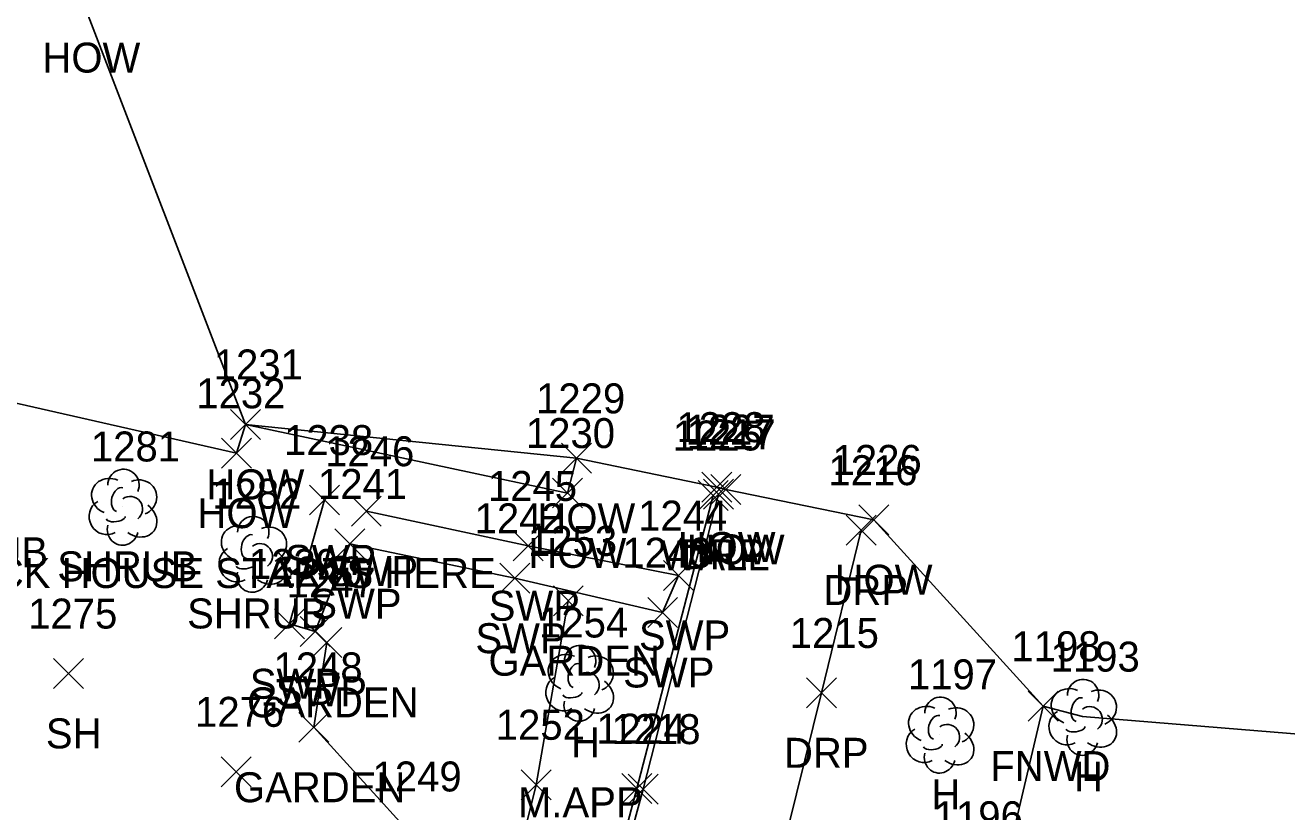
# Model space of a CAD drawing. Extents: x 1616726 to 1619875, y 273782 to 276557.
# Drawn here: x 1617199.2 to 1617283.4, y 276182.4 to 276234.9 of the extents above; entities that cross this region are included whole.
import ezdxf

# ---------------------------------------------------------------- set-up
doc = ezdxf.new("R2010")
doc.units = 0
for name, color, linetype in [('L_A', 7, 'Continuous'), ('L_C', 7, 'Continuous'), ('L_I', 7, 'Continuous'), ('L_TIC', 7, 'Continuous'), ('LAPB', 7, 'Continuous'), ('LBC', 7, 'Continuous'), ('LFNC', 7, 'Continuous'), ('LSH', 7, 'Continuous'), ('LSOGP', 7, 'Continuous'), ('LTD', 7, 'Continuous'), ('LW', 7, 'Continuous'), ('R_A', 7, 'Continuous'), ('R_I', 7, 'Continuous'), ('R_TIC', 7, 'Continuous'), ('RDP', 7, 'Continuous'), ('RSW', 7, 'Continuous')]:
    doc.layers.add(name, color=color, linetype=linetype)

msp = doc.modelspace()

# ---------------------------------------------------------------- linework, layer by layer
at = {"layer": 'L_TIC'}
for points in [[(1617212.935, 276207.22), (1617214.935, 276209.22)], [(1617214.935, 276207.22), (1617212.935, 276209.22)], [(1617212.334, 276205.295), (1617214.334, 276207.295)], [(1617214.334, 276205.295), (1617212.334, 276207.295)], [(1617235.024, 276204.957), (1617237.024, 276206.957)], [(1617237.024, 276204.957), (1617235.024, 276206.957)], [(1617234.421, 276202.64), (1617236.421, 276204.64)], [(1617236.421, 276202.64), (1617234.421, 276204.64)], [(1617244.139, 276202.477), (1617246.139, 276204.477)], [(1617246.139, 276202.477), (1617244.139, 276204.477)], [(1617244.387, 276203.035), (1617246.387, 276205.035)], [(1617246.387, 276203.035), (1617244.387, 276205.035)], [(1617244.993, 276202.869), (1617246.993, 276204.869)], [(1617246.993, 276202.869), (1617244.993, 276204.869)], [(1617254.861, 276200.85), (1617256.861, 276202.85)], [(1617256.861, 276200.85), (1617254.861, 276202.85)], [(1617234.474, 276195.443), (1617236.474, 276197.443)], [(1617236.474, 276195.443), (1617234.474, 276197.443)], [(1617218.364, 276192.666), (1617220.364, 276194.666)], [(1617220.364, 276192.666), (1617218.364, 276194.666)], [(1617201.114, 276190.591), (1617203.114, 276192.591)], [(1617203.114, 276190.591), (1617201.114, 276192.591)], [(1617266.174, 276188.41), (1617268.174, 276190.41)], [(1617268.174, 276188.41), (1617266.174, 276190.41)], [(1617217.488, 276186.997), (1617219.488, 276188.997)], [(1617219.488, 276186.997), (1617217.488, 276188.997)], [(1617212.311, 276184.031), (1617214.311, 276186.031)], [(1617214.311, 276184.031), (1617212.311, 276186.031)], [(1617232.324, 276183.167), (1617234.324, 276185.167)], [(1617234.324, 276183.167), (1617232.324, 276185.167)], [(1617239.042, 276182.91), (1617241.042, 276184.91)], [(1617241.042, 276182.91), (1617239.042, 276184.91)]]:
    msp.add_lwpolyline(points, dxfattribs=at)
at = {"layer": 'LAPB'}
msp.add_lwpolyline([(1617219.364, 276193.666), (1617218.488, 276187.997), (1617225.107, 276180.716), (1617226.271, 276170.776), (1617229.561, 276169.066), (1617233.324, 276184.167), (1617235.474, 276196.443)], dxfattribs=at)
at = {"layer": 'LBC'}
msp.add_lwpolyline([(1617255.861, 276201.85), (1617245.993, 276203.869), (1617245.387, 276204.035), (1617236.024, 276205.957), (1617235.421, 276203.64), (1617213.935, 276208.22), (1617213.334, 276206.295), (1617177.812, 276214.354), (1617179.361, 276218.267), (1617161.118, 276222.362), (1617159.601, 276222.749), (1617139.631, 276227.947)], dxfattribs=at)
at = {"layer": 'LFNC'}
msp.add_lwpolyline([(1617267.174, 276189.41), (1617260.032, 276159.065)], dxfattribs=at)
at = {"layer": 'LSH'}
for p, q in [((1617205.733, 276202.745), (1617205.733, 276202.745)), ((1617205.733, 276202.745), (1617205.733, 276202.745)), ((1617214.4, 276199.599), (1617214.4, 276199.599)), ((1617214.4, 276199.599), (1617214.4, 276199.599))]:
    msp.add_line(p, q, dxfattribs=at)
for centre in [(1617205.78, 276204.179), (1617214.447, 276201.033)]:
    msp.add_arc(centre, 1.047, 335.52715, 180.95627, dxfattribs=at)
for centre, major_axis, ratio, start_param, end_param in [((1617204.942, 276203.412), (1.21, -0.512), 0.895232, 1.570796, 4.712389), ((1617206.775, 276203.329), (-1.141, -0.483), 0.949671, 1.570796, 4.712389), ((1617205.525, 276203.203), (-0.208, -0.792), 0.645439, 3.141593, 6.283185), ((1617204.65, 276202.037), (0.584, -1.042), 0.959034, 3.141593, 6.283185), ((1617206.233, 276202.578), (-0.5, 0.667), 0.989748, 3.141593, 6.283185), ((1617206.734, 276201.912), (-1.09, 0.792), 0.841452, 1.570796, 4.712389), ((1617205.275, 276201.995), (-0.625, -0.083), 0.423636, 0, 3.141593), ((1617205.734, 276201.245), (0.265, 1.061), 0.942809, 1.570796, 4.712389), ((1617213.608, 276200.265), (1.21, -0.512), 0.895232, 1.570796, 4.712389), ((1617215.442, 276200.182), (-1.141, -0.483), 0.949671, 1.570796, 4.712389), ((1617214.192, 276200.057), (-0.208, -0.792), 0.645439, 3.141593, 6.283185), ((1617214.9, 276199.432), (-0.5, 0.667), 0.989748, 3.141593, 6.283185), ((1617213.317, 276198.89), (0.584, -1.042), 0.959034, 3.141593, 6.283185), ((1617215.4, 276198.765), (-1.09, 0.792), 0.841452, 1.570796, 4.712389), ((1617213.942, 276198.849), (-0.625, -0.083), 0.423636, 0, 3.141593), ((1617214.4, 276198.099), (0.265, 1.061), 0.942809, 1.570796, 4.712389)]:
    msp.add_ellipse(centre, major_axis=major_axis, ratio=ratio, start_param=start_param, end_param=end_param, dxfattribs=at)
at = {"layer": 'LSOGP'}
msp.add_lwpolyline([(1617292.925, 276186.82), (1617269.792, 276188.716), (1617267.174, 276189.41), (1617255.861, 276201.85), (1617245.993, 276203.869), (1617245.387, 276204.035), (1617236.024, 276205.957), (1617213.935, 276208.22), (1617202.986, 276236.707)], dxfattribs=at)
at = {"layer": 'LTD'}
for p, q in [((1617236.214, 276190.994), (1617236.214, 276190.994)), ((1617236.214, 276190.994), (1617236.214, 276190.994)), ((1617269.792, 276188.716), (1617269.792, 276188.716)), ((1617269.792, 276188.716), (1617269.792, 276188.716)), ((1617260.267, 276187.532), (1617260.267, 276187.532)), ((1617260.267, 276187.532), (1617260.267, 276187.532))]:
    msp.add_line(p, q, dxfattribs=at)
for centre in [(1617236.261, 276192.428), (1617269.839, 276190.15), (1617260.314, 276188.966)]:
    msp.add_arc(centre, 1.047, 335.52715, 180.95627, dxfattribs=at)
for centre, major_axis, ratio, start_param, end_param in [((1617235.423, 276191.66), (1.21, -0.512), 0.895232, 1.570796, 4.712389), ((1617237.256, 276191.577), (-1.141, -0.483), 0.949671, 1.570796, 4.712389), ((1617236.006, 276191.452), (-0.208, -0.792), 0.645439, 3.141593, 6.283185), ((1617235.131, 276190.285), (0.584, -1.042), 0.959034, 3.141593, 6.283185), ((1617236.714, 276190.827), (-0.5, 0.667), 0.989748, 3.141593, 6.283185), ((1617237.215, 276190.16), (-1.09, 0.792), 0.841452, 1.570796, 4.712389), ((1617235.756, 276190.244), (-0.625, -0.083), 0.423636, 0, 3.141593), ((1617269, 276189.382), (1.21, -0.512), 0.895232, 1.570796, 4.712389), ((1617270.833, 276189.299), (-1.141, -0.483), 0.949671, 1.570796, 4.712389), ((1617236.215, 276189.494), (0.265, 1.061), 0.942809, 1.570796, 4.712389), ((1617259.475, 276188.198), (1.21, -0.512), 0.895232, 1.570796, 4.712389), ((1617261.309, 276188.115), (-1.141, -0.483), 0.949671, 1.570796, 4.712389), ((1617269.583, 276189.174), (-0.208, -0.792), 0.645439, 3.141593, 6.283185), ((1617270.292, 276188.549), (-0.5, 0.667), 0.989748, 3.141593, 6.283185), ((1617260.059, 276187.99), (-0.208, -0.792), 0.645439, 3.141593, 6.283185), ((1617268.709, 276188.007), (0.584, -1.042), 0.959034, 3.141593, 6.283185), ((1617270.792, 276187.883), (-1.09, 0.792), 0.841452, 1.570796, 4.712389), ((1617259.184, 276186.823), (0.584, -1.042), 0.959034, 3.141593, 6.283185), ((1617260.767, 276187.365), (-0.5, 0.667), 0.989748, 3.141593, 6.283185), ((1617261.267, 276186.699), (-1.09, 0.792), 0.841452, 1.570796, 4.712389), ((1617269.334, 276187.966), (-0.625, -0.083), 0.423636, 0, 3.141593), ((1617259.809, 276186.782), (-0.625, -0.083), 0.423636, 0, 3.141593), ((1617269.792, 276187.216), (0.265, 1.061), 0.942809, 1.570796, 4.712389), ((1617260.267, 276186.032), (0.265, 1.061), 0.942809, 1.570796, 4.712389)]:
    msp.add_ellipse(centre, major_axis=major_axis, ratio=ratio, start_param=start_param, end_param=end_param, dxfattribs=at)
at = {"layer": 'LW'}
msp.add_lwpolyline([(1617236.945, 276172.259), (1617240.042, 276183.91), (1617245.139, 276203.477)], dxfattribs=at)
at = {"layer": 'R_TIC'}
for points in [[(1617244.495, 276202.554), (1617246.495, 276204.554)], [(1617246.495, 276202.554), (1617244.495, 276204.554)], [(1617218.195, 276202.173), (1617220.195, 276204.173)], [(1617220.195, 276202.173), (1617218.195, 276204.173)], [(1617220.992, 276201.427), (1617222.992, 276203.427)], [(1617222.992, 276201.427), (1617220.992, 276203.427)], [(1617254.015, 276200.162), (1617256.015, 276202.162)], [(1617256.015, 276200.162), (1617254.015, 276202.162)], [(1617219.89, 276199.243), (1617221.89, 276201.243)], [(1617221.89, 276199.243), (1617219.89, 276201.243)], [(1617231.799, 276199.112), (1617233.799, 276201.112)], [(1617233.799, 276199.112), (1617231.799, 276201.112)], [(1617230.911, 276196.948), (1617232.911, 276198.948)], [(1617232.911, 276196.948), (1617230.911, 276198.948)], [(1617241.827, 276197.13), (1617243.827, 276199.13)], [(1617243.827, 276197.13), (1617241.827, 276199.13)], [(1617240.771, 276194.657), (1617242.771, 276196.657)], [(1617242.771, 276194.657), (1617240.771, 276196.657)], [(1617215.855, 276193.904), (1617217.855, 276195.904)], [(1617217.855, 276193.904), (1617215.855, 276195.904)], [(1617217.584, 276193.395), (1617219.584, 276195.395)], [(1617219.584, 276193.395), (1617217.584, 276195.395)], [(1617251.381, 276189.296), (1617253.381, 276191.296)], [(1617253.381, 276189.296), (1617251.381, 276191.296)], [(1617239.479, 276182.876), (1617241.479, 276184.876)], [(1617241.479, 276182.876), (1617239.479, 276184.876)]]:
    msp.add_lwpolyline(points, dxfattribs=at)
at = {"layer": 'RDP'}
for points in [[(1617245.495, 276203.554), (1617240.479, 276183.876), (1617237.191, 276171.844), (1617234.39, 276160.251)], [(1617244.299, 276157.608), (1617248.51, 276174.647), (1617252.381, 276190.296), (1617255.015, 276201.162)]]:
    msp.add_lwpolyline(points, dxfattribs=at)
at = {"layer": 'RSW'}
msp.add_lwpolyline([(1617219.195, 276203.173), (1617216.855, 276194.904), (1617218.584, 276194.395), (1617220.89, 276200.243), (1617231.911, 276197.948), (1617241.771, 276195.657), (1617242.827, 276198.13), (1617232.799, 276200.112), (1617221.992, 276202.427)], dxfattribs=at)

# ---------------------------------------------------------------- texts
at = {"layer": 'L_A'}
for s, p in [('HOW', (1617200.372, 276231.707)), ('HOW', (1617211.321, 276203.22)), ('HOW', (1617210.72, 276201.295)), ('HOW', (1617233.409, 276200.957)), ('HOW', (1617242.773, 276199.035)), ('SHRUB', (1617191.388, 276198.686)), ('HOW', (1617232.806, 276198.64)), ('WALL', (1617241.627, 276198.477)), ('HOW', (1617243.379, 276198.869)), ('SHRUB', (1617201.363, 276197.745)), ('HOW', (1617253.246, 276196.85)), ('SHRUB', (1617210.03, 276194.599)), ('GARDEN', (1617230.144, 276191.443)), ('GARDEN', (1617214.033, 276188.666)), ('SH', (1617200.602, 276186.591)), ('H', (1617235.647, 276185.994)), ('FNWD', (1617263.639, 276184.41)), ('H', (1617269.225, 276183.716)), ('GARDEN', (1617213.158, 276182.997)), ('H', (1617259.7, 276182.532))]:
    msp.add_text(s, height=2, dxfattribs=at).set_placement(p)
at = {"layer": 'L_C'}
for s, p in [('BRICK HOUSE STARTS HERE', (1617192.735, 276197.295)), ('M.APP', (1617232.112, 276181.994))]:
    msp.add_text(s, height=2, dxfattribs=at).set_placement(p)
at = {"layer": 'L_I'}
for s, p in [('1231', (1617211.809, 276211.22)), ('1232', (1617210.641, 276209.295)), ('1229', (1617233.323, 276208.957)), ('1230', (1617232.641, 276206.64)), ('1228', (1617242.694, 276207.035)), ('1227', (1617243.3, 276206.869)), ('1225', (1617242.446, 276206.477)), ('1281', (1617203.607, 276205.745)), ('1226', (1617253.113, 276204.85)), ('1282', (1617211.707, 276202.599)), ('1253', (1617232.781, 276199.443)), ('1247', (1617216.671, 276196.666)), ('1275', (1617199.421, 276194.591)), ('1254', (1617233.521, 276193.994)), ('1198', (1617265.048, 276192.41)), ('1193', (1617267.666, 276191.716)), ('1248', (1617215.795, 276190.997)), ('1197', (1617258.141, 276190.532)), ('1276', (1617210.563, 276188.031)), ('1252', (1617230.631, 276187.167)), ('1224', (1617237.349, 276186.91)), ('1249', (1617222.406, 276183.716)), ('1196', (1617259.86, 276181.06))]:
    msp.add_text(s, height=2, dxfattribs=at).set_placement(p)
at = {"layer": 'R_A'}
for s, p in [('SWP', (1617216.557, 276198.173)), ('DRP', (1617242.983, 276198.554)), ('SWP', (1617219.354, 276197.427)), ('DRP', (1617252.503, 276196.162)), ('SWP', (1617218.253, 276195.243)), ('SWP', (1617230.161, 276195.112)), ('SWP', (1617240.189, 276193.13)), ('SWP', (1617229.273, 276192.948)), ('SWP', (1617239.134, 276190.657)), ('SWP', (1617214.217, 276189.904)), ('SWP', (1617215.946, 276189.395)), ('DRP', (1617249.87, 276185.296))]:
    msp.add_text(s, height=2, dxfattribs=at).set_placement(p)
at = {"layer": 'R_I'}
for s, p in [('1238', (1617216.502, 276206.173)), ('1217', (1617243.369, 276206.554)), ('1246', (1617219.244, 276205.427)), ('1216', (1617252.834, 276204.162)), ('1241', (1617218.764, 276203.243)), ('1245', (1617230.106, 276203.112)), ('1242', (1617229.218, 276200.948)), ('1244', (1617240.134, 276201.13)), ('1243', (1617239.079, 276198.657)), ('1239', (1617214.154, 276197.904)), ('1240', (1617215.804, 276197.395)), ('1215', (1617250.255, 276193.296)), ('1218', (1617238.353, 276186.876))]:
    msp.add_text(s, height=2, dxfattribs=at).set_placement(p)

doc.saveas('drawing.dxf')
